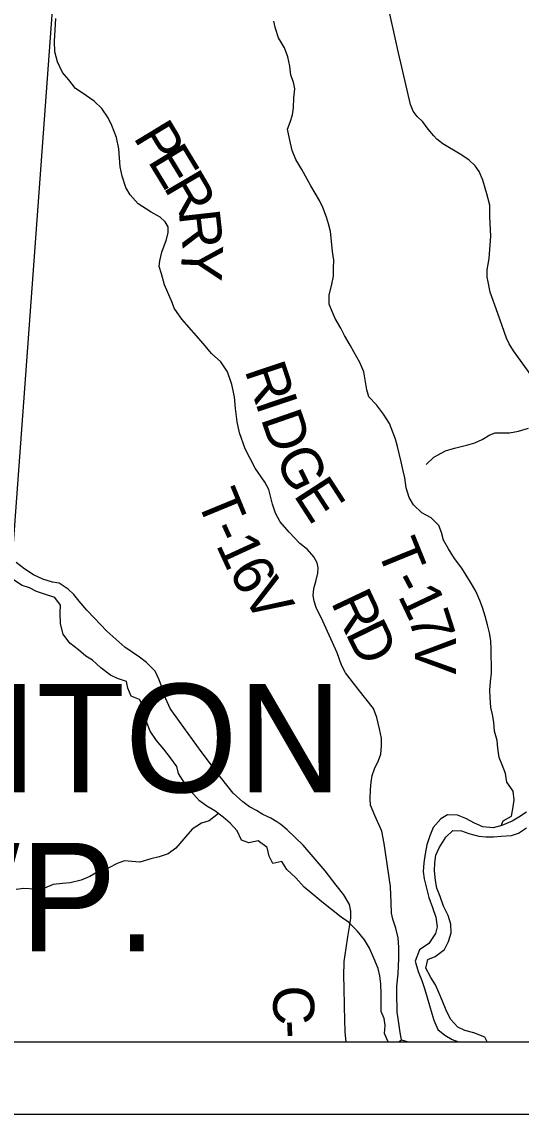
# Model space of a CAD drawing. Extents: x -8.2 to 34, y 0 to 22.
# Drawn here: x 3.185 to 3.876, y 14 to 15.511 of the extents above; entities that cross this region are included whole.
import ezdxf

# ---------------------------------------------------------------- set-up
doc = ezdxf.new("R2010")
doc.units = 0
for name, color, linetype in [('GM_X_Corporation', 7, 'Continuous'), ('GM_X_County_Road', 7, 'Continuous'), ('GM_X_County_Road_Text', 7, 'Continuous'), ('GM_X_Major_River', 7, 'Continuous'), ('GM_X_Minor_River', 7, 'Continuous'), ('GM_X_Township_Road', 7, 'Continuous'), ('GM_X_Township_Road_Text', 7, 'Continuous'), ('GM_X_Township_Text', 7, 'Continuous'), ('SH_Data', 7, 'Continuous')]:
    doc.layers.add(name, color=color, linetype=linetype)

msp = doc.modelspace()

# ---------------------------------------------------------------- linework, layer by layer
at = {"layer": 'GM_X_Corporation'}
msp.add_lwpolyline([(2.1, 20.9), (2.1, 14.1), (4.1481, 14.1), (4.1604, 14.3288), (4.1741, 14.5315), (4.1846, 14.6878), (4.2113, 15.0848), (4.2352, 15.4906), (4.2558, 15.6585), (4.2674, 15.658), (4.2922, 15.6569), (4.4152, 15.6505), (4.4836, 15.6492), (5.4088, 15.5882), (6.2987, 15.5287), (6.3333, 15.9036), (6.368, 16.4128), (6.4323, 17.3579)], dxfattribs=at)
msp.add_lwpolyline([(2.2302, 15.7835), (3.2411, 15.7231), (3.1659, 14.6948), (2.1717, 14.7662)], close=True, dxfattribs=at)
at = {"layer": 'GM_X_County_Road'}
msp.add_lwpolyline([(3.6336, 14.1), (3.6319, 14.1133), (3.6314, 14.1485), (3.6306, 14.1762), (3.6301, 14.1902), (3.6307, 14.2112), (3.6334, 14.2296), (3.6358, 14.2451), (3.6383, 14.2589), (3.6398, 14.2712), (3.64, 14.2809), (3.6383, 14.2902), (3.6304, 14.3033), (3.6197, 14.3168), (3.6044, 14.3367), (3.5742, 14.3719), (3.5518, 14.3933), (3.5432, 14.4007), (3.5377, 14.4045), (3.5293, 14.4094), (3.5184, 14.4147), (3.5095, 14.4199), (3.4997, 14.4253), (3.4904, 14.4319), (3.477, 14.4441), (3.4613, 14.464), (3.433, 14.5015), (3.403, 14.5429), (3.3901, 14.561), (3.384, 14.5745), (3.3793, 14.5885), (3.3747, 14.6007), (3.3691, 14.6128), (3.3571, 14.6245), (3.3475, 14.6319), (3.3273, 14.6459), (3.3025, 14.6681), (3.285, 14.6867), (3.2747, 14.6969), (3.264, 14.7096), (3.2567, 14.7186), (3.2487, 14.7263), (3.2363, 14.7344), (3.2271, 14.736), (3.2136, 14.74), (3.201, 14.7459), (3.1887, 14.754), (3.1768, 14.763)], dxfattribs=at)
at = {"layer": 'GM_X_Major_River'}
for points in [[(3.8832, 14.4178), (3.8726, 14.411), (3.8631, 14.4053), (3.849, 14.3993), (3.8369, 14.3962), (3.8228, 14.3974), (3.811, 14.4023), (3.7993, 14.4088), (3.7875, 14.4137), (3.7738, 14.4141), (3.7644, 14.4084), (3.7541, 14.3963), (3.7491, 14.3849), (3.7453, 14.3724), (3.7427, 14.3599), (3.7411, 14.3477), (3.74, 14.3356), (3.7415, 14.3257), (3.7479, 14.2999), (3.7528, 14.2859), (3.7574, 14.2726), (3.7593, 14.2593), (3.757, 14.2498), (3.7478, 14.2362), (3.7349, 14.2271), (3.7288, 14.2115), (3.733, 14.1975), (3.7383, 14.185), (3.7421, 14.174), (3.7455, 14.1615), (3.7489, 14.1501), (3.7519, 14.1394), (3.7549, 14.13), (3.7602, 14.117), (3.7701, 14.1091), (3.78, 14.1034), (3.789, 14.1)], [(3.8285, 14.1), (3.8252, 14.1064), (3.8104, 14.1125), (3.7978, 14.1155), (3.788, 14.1204), (3.7777, 14.1315), (3.772, 14.144), (3.7667, 14.1565), (3.7618, 14.1683), (3.7573, 14.1789), (3.7508, 14.1888), (3.7436, 14.2017), (3.7467, 14.2138), (3.7566, 14.218), (3.7695, 14.2278), (3.7752, 14.2388), (3.779, 14.2506), (3.7782, 14.2627), (3.7745, 14.2749), (3.768, 14.2878), (3.7635, 14.3011), (3.7589, 14.3124), (3.757, 14.3234), (3.7559, 14.3367), (3.7563, 14.3477), (3.7578, 14.3584), (3.7624, 14.3682), (3.7715, 14.383), (3.781, 14.3925), (3.7932, 14.3917), (3.8034, 14.3883), (3.8171, 14.3845), (3.8266, 14.3837), (3.8376, 14.3837), (3.8482, 14.3845), (3.8623, 14.3856), (3.8718, 14.3886), (3.8832, 14.3962)]]:
    msp.add_lwpolyline(points, dxfattribs=at)
at = {"layer": 'GM_X_Minor_River'}
for points in [[(3.8478, 14.399), (3.8508, 14.4059), (3.8622, 14.4124), (3.8648, 14.4249), (3.8659, 14.4347), (3.8644, 14.4469), (3.856, 14.4594), (3.8541, 14.4711), (3.8492, 14.4832), (3.8454, 14.4931), (3.8435, 14.5064), (3.8423, 14.5166), (3.8389, 14.5299), (3.8378, 14.542), (3.8362, 14.5526), (3.8339, 14.5625), (3.8328, 14.5765), (3.8324, 14.5863), (3.8331, 14.5981), (3.8346, 14.6098), (3.8346, 14.6224), (3.8342, 14.6326), (3.8342, 14.6421), (3.8338, 14.655), (3.8319, 14.6659), (3.8293, 14.6766), (3.8258, 14.6887), (3.822, 14.7008), (3.8186, 14.7103), (3.8129, 14.7232), (3.8057, 14.736), (3.7936, 14.755), (3.7833, 14.7686), (3.775, 14.7819), (3.7681, 14.794), (3.7655, 14.8046), (3.7617, 14.8141), (3.7511, 14.8247), (3.7382, 14.8319), (3.7268, 14.8428), (3.7207, 14.8531), (3.7165, 14.8663), (3.7146, 14.88), (3.7123, 14.8898), (3.7097, 14.9023), (3.7044, 14.9236), (3.7017, 14.9334), (3.6983, 14.9433), (3.6933, 14.9554), (3.6854, 14.9683), (3.6755, 14.9812), (3.6649, 14.9921), (3.6622, 15.002), (3.6603, 15.013), (3.658, 15.0266), (3.6523, 15.0395), (3.6443, 15.0543), (3.639, 15.0638), (3.6314, 15.077), (3.6261, 15.0872), (3.6182, 15.1005), (3.614, 15.11), (3.6102, 15.1202), (3.6102, 15.1327), (3.6139, 15.1479), (3.6158, 15.1593), (3.6162, 15.1699), (3.6165, 15.1813), (3.6146, 15.193), (3.6131, 15.2074), (3.612, 15.2207), (3.6089, 15.2313), (3.6062, 15.2408), (3.6013, 15.254), (3.5967, 15.2639), (3.5907, 15.2737), (3.5846, 15.284), (3.5797, 15.2934), (3.5721, 15.3067), (3.5637, 15.3203), (3.5588, 15.3328), (3.5554, 15.3472), (3.5523, 15.3624), (3.5561, 15.3723), (3.5591, 15.3821), (3.5606, 15.392), (3.561, 15.4056), (3.5625, 15.4181), (3.5606, 15.4276), (3.5568, 15.4371), (3.5556, 15.4496), (3.5526, 15.4625), (3.5484, 15.475), (3.54, 15.4886), (3.5355, 15.5015), (3.5332, 15.5118)], [(3.6915, 14.1), (3.6864, 14.1115), (3.6875, 14.1228), (3.6863, 14.1323), (3.6818, 14.1422), (3.6818, 14.1524), (3.6821, 14.1661), (3.6817, 14.1801), (3.6802, 14.1911), (3.6776, 14.2013), (3.6719, 14.2157), (3.6658, 14.2294), (3.6589, 14.2411), (3.6487, 14.2536), (3.6366, 14.2657), (3.6267, 14.2725), (3.6134, 14.2831), (3.5998, 14.2937), (3.5861, 14.3051), (3.5755, 14.3141), (3.5638, 14.327), (3.5513, 14.3384), (3.5444, 14.3494), (3.5319, 14.3467), (3.527, 14.3569), (3.5243, 14.369), (3.5118, 14.3781), (3.4989, 14.3751), (3.4887, 14.3792), (3.4826, 14.3917), (3.4731, 14.4027), (3.4633, 14.4107), (3.4519, 14.4194), (3.4405, 14.4258), (3.4307, 14.4334), (3.4182, 14.447), (3.4102, 14.4572), (3.4015, 14.4712), (3.3992, 14.4807), (3.3905, 14.4928), (3.3814, 14.5049), (3.3711, 14.5167), (3.3624, 14.5299), (3.3582, 14.5402), (3.3563, 14.5496), (3.3536, 14.5618), (3.3476, 14.5735), (3.3362, 14.578), (3.3313, 14.589), (3.3297, 14.5985), (3.3172, 14.6027), (3.3074, 14.6072), (3.2941, 14.6174), (3.2827, 14.628), (3.2732, 14.6337), (3.263, 14.6424), (3.2509, 14.6515), (3.2421, 14.664), (3.238, 14.6784), (3.2376, 14.6935), (3.2383, 14.7038), (3.2303, 14.7144), (3.2175, 14.7189), (3.205, 14.7231), (3.1951, 14.728), (3.1853, 14.7314), (3.1731, 14.7389)], [(3.4568, 14.4157), (3.444, 14.4057), (3.4334, 14.4023), (3.4205, 14.3943), (3.4088, 14.381), (3.3978, 14.3681), (3.3872, 14.3601), (3.3747, 14.3559), (3.363, 14.3533), (3.3482, 14.3487), (3.3368, 14.3494), (3.327, 14.3502), (3.3168, 14.3468), (3.3043, 14.3403), (3.2899, 14.335), (3.2789, 14.3285), (3.2668, 14.3236), (3.2516, 14.3198), (3.241, 14.319), (3.2282, 14.3175), (3.216, 14.3125), (3.2028, 14.3113), (3.1876, 14.3121), (3.1767, 14.3106)]]:
    msp.add_lwpolyline(points, dxfattribs=at)
at = {"layer": 'GM_X_Township_Road'}
msp.add_line((3.71, 14.1028), (3.7193, 14.1), dxfattribs=at)
for points in [[(3.704, 15.4762), (3.6913, 15.5344), (3.6864, 15.5433), (3.6716, 15.5692), (3.6613, 15.5922), (3.6539, 15.6285), (3.6367, 15.6936)], [(3.7059, 14.1), (3.71, 14.1028), (3.7084, 14.1128), (3.7057, 14.1323), (3.7039, 14.1411), (3.7036, 14.1683), (3.7036, 14.177), (3.7053, 14.1943), (3.7062, 14.2155), (3.7066, 14.2304), (3.7056, 14.2439), (3.7023, 14.2573), (3.6982, 14.2699), (3.6964, 14.278), (3.6959, 14.2923), (3.695, 14.3151), (3.6863, 14.3742), (3.683, 14.3915), (3.6732, 14.4132), (3.6674, 14.4275), (3.6666, 14.4362), (3.6673, 14.449), (3.6681, 14.4592), (3.6694, 14.4686), (3.6727, 14.4776), (3.6781, 14.489), (3.6814, 14.498), (3.6826, 14.5096), (3.6824, 14.5199), (3.6796, 14.5331), (3.6761, 14.5485), (3.6712, 14.561), (3.6503, 14.5878), (3.6326, 14.6104), (3.627, 14.6211), (3.6209, 14.6383), (3.601, 14.6818), (3.5918, 14.701), (3.5891, 14.7094), (3.5877, 14.7174), (3.5886, 14.7273), (3.5914, 14.7367), (3.5944, 14.7482), (3.5947, 14.7556), (3.5932, 14.7628), (3.589, 14.7709), (3.5799, 14.7809), (3.5696, 14.7893), (3.5546, 14.8051), (3.5424, 14.8194), (3.5358, 14.8313), (3.5317, 14.8439), (3.5299, 14.8513), (3.5265, 14.864), (3.521, 14.8743), (3.5074, 14.8934), (3.4939, 14.9202), (3.486, 14.9424), (3.4827, 14.9577), (3.4803, 14.9762), (3.4789, 14.9924), (3.4753, 15.0094), (3.4692, 15.0268), (3.4602, 15.0405), (3.4472, 15.0523), (3.4362, 15.0655), (3.4059, 15.0995), (3.3957, 15.115), (3.3926, 15.1227), (3.3819, 15.1472), (3.3781, 15.1623), (3.3748, 15.1724), (3.3758, 15.1804), (3.3783, 15.1921), (3.3849, 15.2099), (3.3873, 15.2197), (3.387, 15.2273), (3.3829, 15.2342), (3.376, 15.2408), (3.3638, 15.2474), (3.3459, 15.259), (3.3345, 15.2717), (3.3284, 15.2819), (3.3237, 15.2972), (3.3209, 15.3102), (3.3189, 15.3352), (3.3158, 15.351), (3.3094, 15.3673), (3.3043, 15.3781), (3.2952, 15.3911), (3.2849, 15.4013), (3.2683, 15.4125), (3.2589, 15.4187), (3.2497, 15.4306), (3.2411, 15.4409), (3.2342, 15.4556), (3.2305, 15.4693), (3.2299, 15.484), (3.2316, 15.5156)], [(3.8906, 15.0209), (3.8712, 15.0475), (3.8649, 15.0556), (3.8589, 15.0653), (3.8554, 15.0735), (3.8436, 15.1076), (3.8329, 15.1368), (3.8301, 15.1513), (3.8288, 15.1579), (3.8286, 15.1679), (3.8312, 15.1837), (3.8335, 15.2146), (3.8325, 15.2414), (3.8321, 15.2571), (3.8281, 15.273), (3.8225, 15.2921), (3.8176, 15.3039), (3.8122, 15.3118), (3.8034, 15.3202), (3.7913, 15.328), (3.7673, 15.3421), (3.759, 15.3484), (3.7549, 15.3534), (3.7469, 15.3625), (3.7395, 15.3724), (3.7319, 15.3801), (3.7263, 15.3873), (3.7227, 15.3965), (3.7181, 15.4164), (3.7044, 15.4742), (3.704, 15.4762)], [(3.7441, 14.8985), (3.7546, 14.9087), (3.771, 14.9176), (3.7835, 14.9212), (3.8021, 14.9258), (3.8115, 14.9285), (3.8215, 14.9332), (3.8321, 14.9398), (3.8398, 14.9426), (3.8495, 14.9423), (3.8594, 14.9424), (3.8722, 14.9447), (3.8857, 14.9487)]]:
    msp.add_lwpolyline(points, dxfattribs=at)
at = {"layer": 'SH_Data'}
for p, q in [((2.1, 14.1), (4.1481, 14.1)), ((2, 14), (9, 14))]:
    msp.add_line(p, q, dxfattribs=at)

# ---------------------------------------------------------------- texts
at = {"layer": 'GM_X_County_Road_Text'}
for s, rotation, p in [('C', 271.0538, (3.532, 14.1776)), ('-', 272.8317, (3.5329, 14.129))]:
    msp.add_text(s, height=0.0568, rotation=rotation, dxfattribs=at).set_placement(p)
at = {"layer": 'GM_X_Township_Road_Text'}
for s, rotation, p in [('P', 301.2751, (3.3381, 15.3513)), ('E', 301.2717, (3.358, 15.3186)), ('R', 300.3888, (3.3799, 15.2825)), ('R', 276.4458, (3.4016, 15.2481)), ('Y', 267.5076, (3.4067, 15.2041)), ('R', 288.5325, (3.4925, 15.0292)), ('I', 288.5317, (3.5073, 14.985)), ('D', 289.0989, (3.5149, 14.9623)), ('G', 295.9401, (3.5341, 14.9082)), ('E', 302.9715, (3.5597, 14.8566)), ('T', 292.3776, (3.426, 14.8504)), ('-', 294.4616, (3.4431, 14.809)), ('1', 294.6608, (3.4528, 14.7876)), ('T', 292.1372, (3.6751, 14.7822)), ('6', 299.606, (3.4698, 14.7511)), ('V', 302.2015, (3.4886, 14.7182)), ('-', 297.9278, (3.6938, 14.7372)), ('1', 295.385, (3.7044, 14.7172)), ('R', 295.2838, (3.6117, 14.7084)), ('7', 287.8014, (3.7187, 14.6874)), ('D', 296.0196, (3.6319, 14.6655)), ('V', 270.1239, (3.7287, 14.6586))]:
    msp.add_text(s, height=0.0568, rotation=rotation, dxfattribs=at).set_placement(p)
at = {"layer": 'GM_X_Township_Text'}
for s, p in [('VINTON', (2.8704, 14.4452)), ('TWP.', (2.8704, 14.2252))]:
    msp.add_text(s, height=0.15, rotation=0, dxfattribs=at).set_placement(p)

doc.saveas('drawing.dxf')
